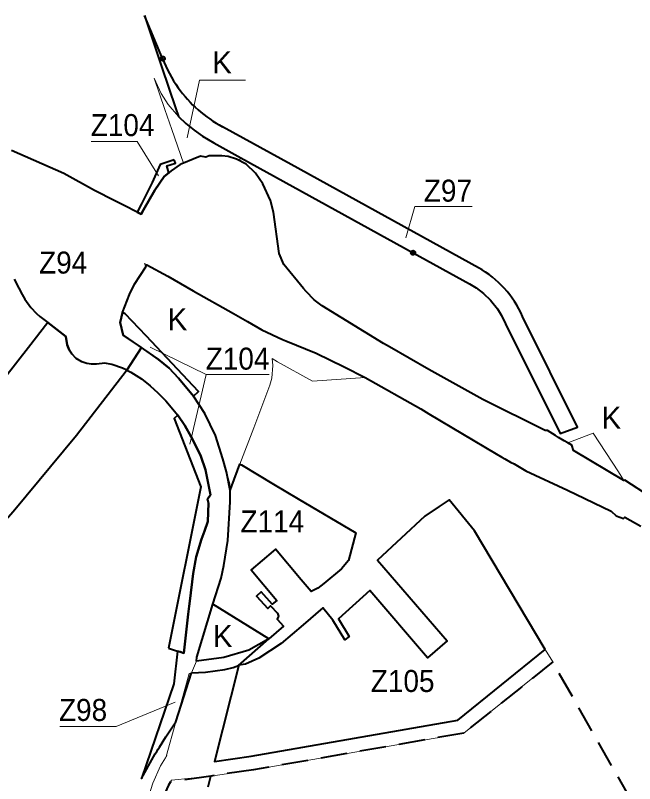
# Model space of a CAD drawing. Extents: x -650276 to -642489, y -1074311 to -1066658.
# Drawn here: x -646740 to -646064, y -1069193 to -1068354 of the extents above; entities that cross this region are included whole.
import ezdxf

# ---------------------------------------------------------------- set-up
doc = ezdxf.new("R2010")
doc.units = 0
doc.header["$LTSCALE"] = 9.6
doc.header["$PDMODE"] = 32
doc.header["$PDSIZE"] = 4.8
doc.linetypes.add('MEDIUM_DASHED', pattern=[4.5, 3, -1.5])
for name, color, linetype, lineweight in [('44', 7, 'Continuous', 40), ('45', 7, 'Continuous', 40), ('46', 7, 'Continuous', 13), ('47', 7, 'Continuous', 13), ('48', 7, 'Continuous', 13), ('61', 7, 'MEDIUM_DASHED', 40)]:
    doc.layers.add(name, color=color, linetype=linetype, lineweight=lineweight)

msp = doc.modelspace()

# ---------------------------------------------------------------- linework, layer by layer
at = {"layer": '44'}
msp.add_line((-646578.881, -1068401.54), (-646598.635, -1068354.436), dxfattribs=at)
for points in [[(-646598.635, -1068354.436), (-646579.62, -1068411.29), (-646564.78, -1068455.41), (-646561.544, -1068464.842)], [(-646561.544, -1068464.842), (-646553.677, -1068472.283), (-646544.525, -1068479.79), (-646535.245, -1068486.342), (-646523.105, -1068493.54), (-646493.511, -1068509.855), (-646305.678, -1068613.404)], [(-646234.342, -1068629.893), (-646234.342, -1068629.892), (-646438.626, -1068517.274), (-646513.45, -1068476.025), (-646513.567, -1068475.963)], [(-646545.57, -1068511.42), (-646556.22, -1068515.84), (-646559.72, -1068517.29), (-646569.61, -1068524.1), (-646572.02, -1068526.07), (-646577.07, -1068530.2), (-646587.28, -1068545.28), (-646599.75, -1068566.49), (-646602.21, -1068571.5), (-646606.59, -1068569.33), (-646620.94, -1068561.96), (-646625.86, -1068559.47), (-646631.18, -1068556.77), (-646653.21, -1068545.58), (-646686.84, -1068526.89), (-646686.84, -1068526.89), (-646743.69, -1068501.76)], [(-646337.93, -1068712.4), (-646404.83, -1068671.52), (-646413.45, -1068664.71), (-646422.32, -1068655.58), (-646425.11, -1068652.37), (-646446.54, -1068626.14), (-646451.82, -1068614.31), (-646458.03, -1068569.26), (-646461.14, -1068556.34), (-646469.51, -1068538.15), (-646477.41, -1068526.45), (-646487.92, -1068516.87), (-646498.48, -1068511.26), (-646507.4, -1068508.45), (-646514.39, -1068507.56), (-646528.18, -1068507.58), (-646531.9, -1068509.25), (-646537.71, -1068508.16), (-646545.57, -1068511.42)], [(-646305.678, -1068613.404), (-646243.997, -1068647.407), (-646236.707, -1068651.891), (-646228.691, -1068658.051), (-646221.348, -1068665.144), (-646213.659, -1068674.696), (-646209.179, -1068681.795), (-646204.654, -1068690.937), (-646145.083, -1068810.83), (-646126.317, -1068803.654), (-646186.371, -1068682.825)], [(-646602.095, -1068716.98), (-646622.01, -1068703.3), (-646625.35, -1068689.7), (-646622.68, -1068678.75), (-646615.19, -1068659.11), (-646609.7, -1068647.84), (-646597.4, -1068628.74), (-646596.28, -1068626.52), (-646596.28, -1068626.52), (-646573.14, -1068638.98), (-646545.73, -1068654.81), (-646545.73, -1068654.81), (-646501.64, -1068679.81), (-646486.23, -1068688.54), (-646470.65, -1068697.38), (-646448.02, -1068707.99), (-646444.51, -1068709.64), (-646411.3, -1068723.11), (-646380.94, -1068737.81), (-646357.87, -1068749.64), (-646297.08, -1068783.8), (-646288.37, -1068789.04), (-646251.73, -1068811.04), (-646214.92, -1068832.85), (-646208.7, -1068836.39), (-646205.48, -1068838.23), (-646199.24, -1068841.79), (-646195.52, -1068843.92), (-646182.57, -1068851.3), (-646137.23, -1068872.6), (-646089.63, -1068895.5), (-646084.1, -1068900.51), (-646076.09, -1068903.48), (-646074.51, -1068901.9), (-646057.13, -1068911.62)], [(-646740.91, -1068642.34), (-646735.62, -1068652.21), (-646732.25, -1068659.06), (-646729.34, -1068663.94), (-646722.6, -1068673.11), (-646716.39, -1068679.8), (-646716.39, -1068679.8), (-646712.93, -1068683), (-646704.316, -1068689.698), (-646684.7, -1068704.95), (-646682.98, -1068714.07), (-646680.88, -1068719.28), (-646678.08, -1068723.7)], [(-646704.316, -1068689.698), (-646725.374, -1068716.786), (-646751.116, -1068749.975), (-646817.718, -1068830.545), (-646855.506, -1068872.883), (-646894.206, -1068911.595), (-646934.465, -1068940.759)], [(-646617.991, -1068741.504), (-646622.62, -1068739.32), (-646634.37, -1068735.27), (-646642.04, -1068733.74), (-646651.21, -1068734.99), (-646656.47, -1068735.13), (-646661.5, -1068734.35), (-646667.17, -1068732.38), (-646673.16, -1068728.69), (-646678.08, -1068723.7), (-646680.88, -1068719.28), (-646682.98, -1068714.07), (-646684.7, -1068704.95), (-646704.316, -1068689.698)], [(-646046.48, -1068879.92), (-646074.78, -1068861.51), (-646075.56, -1068861.95), (-646130.68, -1068829.21), (-646132.62, -1068823.54), (-646136.99, -1068820.88), (-646140.73, -1068818.61), (-646146.85, -1068814.88), (-646150.26, -1068812.81), (-646159.1, -1068807.43), (-646161.45, -1068807.54), (-646229.44, -1068773.53), (-646288.59, -1068740.88), (-646331.26, -1068716.25), (-646337.93, -1068712.4)], [(-646618.655, -1068742.359), (-646617.991, -1068741.504), (-646617.991, -1068741.503), (-646602.095, -1068716.98)], [(-646539.08, -1068779.481), (-646545.32, -1068769.89), (-646561.5, -1068750.22), (-646571.91, -1068739.54), (-646583.49, -1068729.76), (-646602.095, -1068716.98), (-646617.991, -1068741.503)], [(-647065.688, -1069087.73), (-646978.92, -1069073.93), (-646929.186, -1069052.925), (-646880.163, -1069024.903), (-646829.104, -1068987.917), (-646782.784, -1068941.581), (-646741.85, -1068895.719), (-646673.05, -1068812.491), (-646618.655, -1068742.359), (-646617.991, -1068741.504)], [(-646617.991, -1068741.503), (-646613.44, -1068743.65), (-646601.86, -1068751.01), (-646592.53, -1068758.66), (-646583.98, -1068766.42), (-646575.28, -1068775.04), (-646562.49, -1068790.69), (-646554.8, -1068801.98)], [(-646509.323, -1068852.529), (-646513.27, -1068838.37), (-646521.18, -1068812.95), (-646532.92, -1068788.95), (-646539.08, -1068779.481)], [(-646554.8, -1068801.98), (-646547.68, -1068814.22), (-646547.433, -1068814.73)], [(-646547.433, -1068814.73), (-646537.35, -1068835.56), (-646532.16, -1068850.47), (-646526.64, -1068877.47), (-646530.06, -1068882.16)], [(-646524, -1068997), (-646514.91, -1068968.48), (-646514.91, -1068968.48), (-646512.07, -1068954.68), (-646507.91, -1068927.47), (-646505.12, -1068885.31), (-646505.17, -1068872.78), (-646509.323, -1068852.529)], [(-646530.06, -1068882.16), (-646528.92, -1068886.55), (-646529.44, -1068906.81), (-646533.28, -1068917.17)], [(-646533.28, -1068917.17), (-646536.54, -1068925.95), (-646542.16, -1068945.12), (-646545.42, -1068963.3), (-646549.17, -1068993.71), (-646549.81, -1068998.88), (-646550.89, -1069007.7), (-646555.84, -1069050.22), (-646559.8, -1069048.98), (-646562.61, -1069048.08)], [(-646462.98, -1069034.61), (-646485, -1069047), (-646512, -1069055), (-646542, -1069059), (-646541.71, -1069054.76), (-646524, -1068997)], [(-646547.412, -1069071.71), (-646532, -1069071), (-646511, -1069068), (-646502, -1069066), (-646496.317, -1069063.61), (-646462.98, -1069034.61)], [(-646562.61, -1069048.08), (-646566.82, -1069083.62), (-646601.82, -1069187.25), (-646586.97, -1069160.06), (-646585.42, -1069157.56), (-646583.89, -1069155.1), (-646582.46, -1069152.81), (-646582.46, -1069152.81), (-646575.4, -1069141.46), (-646564.54, -1069125.08), (-646547.412, -1069071.71)]]:
    msp.add_lwpolyline(points, dxfattribs=at)
at = {"layer": '44', "lineweight": 13}
for points in [[(-646241.379, -1068562.947), (-646303.746, -1068562.947), (-646313.477, -1068597.03)], [(-646241.379, -1068562.947), (-646303.746, -1068562.947), (-646313.477, -1068597.03)], [(-646691.216, -1069130.395), (-646629.734, -1069130.395), (-646565.156, -1069103.837)], [(-646691.216, -1069130.395), (-646629.734, -1069130.395), (-646565.156, -1069103.837)]]:
    msp.add_lwpolyline(points, dxfattribs=at)
at = {"layer": '44'}
for centre, radius, start, end in [((-646447.332, -1068351.964), 140.58, 200.6496, 215.36619), ((-646447.332, -1068351.964), 140.58, 215.36631, 241.891), ((-646287.447, -1068726.224), 110, 23.23727, 61.13296)]:
    msp.add_arc(centre, radius, start, end, dxfattribs=at)
for p in [(-646578.881, -1068401.54), (-646305.678, -1068613.404)]:
    msp.add_point(p, dxfattribs=at)
at = {"layer": '45'}
msp.add_line((-646583.49, -1068729.76), (-646571.91, -1068739.54), dxfattribs=at)
msp.add_line((-646583.49, -1068729.76), (-646571.91, -1068739.54), dxfattribs=at)
for points in [[(-646566.33, -1068512.04), (-646581.64, -1068517.24), (-646590.31, -1068536.69), (-646602.01, -1068560.15), (-646606.59, -1068569.33)], [(-646566.33, -1068512.04), (-646581.64, -1068517.24), (-646590.31, -1068536.69), (-646602.01, -1068560.15), (-646606.59, -1068569.33)], [(-646587.28, -1068545.28), (-646577.07, -1068530.2), (-646572.02, -1068526.07), (-646574.48, -1068518.75), (-646565.04, -1068515.86), (-646566.33, -1068512.04)], [(-646587.28, -1068545.28), (-646577.07, -1068530.2), (-646572.02, -1068526.07), (-646574.48, -1068518.75), (-646565.04, -1068515.86), (-646566.33, -1068512.04)], [(-646599.75, -1068566.49), (-646587.28, -1068545.28), (-646587.28, -1068545.28)], [(-646599.75, -1068566.49), (-646587.28, -1068545.28), (-646587.28, -1068545.28)], [(-646606.59, -1068569.33), (-646602.21, -1068571.5), (-646599.75, -1068566.49)], [(-646606.59, -1068569.33), (-646602.21, -1068571.5), (-646599.75, -1068566.49)], [(-646571.91, -1068739.54), (-646561.5, -1068750.22), (-646545.32, -1068769.89), (-646539.78, -1068764.65), (-646596.93, -1068704.15), (-646619.74, -1068680.15), (-646622.68, -1068678.75), (-646625.35, -1068689.7)], [(-646571.91, -1068739.54), (-646561.5, -1068750.22), (-646545.32, -1068769.89), (-646539.78, -1068764.65), (-646596.93, -1068704.15), (-646619.74, -1068680.15), (-646622.68, -1068678.75), (-646625.35, -1068689.7)], [(-646625.35, -1068689.7), (-646622.01, -1068703.3), (-646583.49, -1068729.76)], [(-646625.35, -1068689.7), (-646622.01, -1068703.3), (-646583.49, -1068729.76)], [(-646562.49, -1068790.69), (-646566.34, -1068794.32), (-646537.3, -1068868.95), (-646572.42, -1069044.94)], [(-646562.49, -1068790.69), (-646566.34, -1068794.32), (-646537.3, -1068868.95), (-646572.42, -1069044.94)], [(-646526.64, -1068877.47), (-646532.16, -1068850.47), (-646537.35, -1068835.56), (-646547.68, -1068814.22), (-646554.8, -1068801.98), (-646562.49, -1068790.69)], [(-646526.64, -1068877.47), (-646532.16, -1068850.47), (-646537.35, -1068835.56), (-646547.68, -1068814.22), (-646554.8, -1068801.98), (-646562.49, -1068790.69)], [(-646529.44, -1068906.81), (-646528.92, -1068886.55), (-646530.06, -1068882.16), (-646526.64, -1068877.47)], [(-646529.44, -1068906.81), (-646528.92, -1068886.55), (-646530.06, -1068882.16), (-646526.64, -1068877.47)], [(-646555.84, -1069050.22), (-646550.89, -1069007.7), (-646549.81, -1068998.88), (-646549.17, -1068993.71), (-646545.42, -1068963.3), (-646542.16, -1068945.12), (-646536.54, -1068925.95), (-646533.28, -1068917.17), (-646529.44, -1068906.81)], [(-646555.84, -1069050.22), (-646550.89, -1069007.7), (-646549.81, -1068998.88), (-646549.17, -1068993.71), (-646545.42, -1068963.3), (-646542.16, -1068945.12), (-646536.54, -1068925.95), (-646533.28, -1068917.17), (-646529.44, -1068906.81)], [(-646572.42, -1069044.94), (-646562.61, -1069048.08), (-646559.8, -1069048.98), (-646555.84, -1069050.22)], [(-646572.42, -1069044.94), (-646562.61, -1069048.08), (-646559.8, -1069048.98), (-646555.84, -1069050.22)]]:
    msp.add_lwpolyline(points, dxfattribs=at)
for points in [[(-646512.07, -1068954.68), (-646507.91, -1068927.47), (-646505.12, -1068885.31), (-646505.17, -1068872.78), (-646503.24, -1068867.61), (-646494.52, -1068844.29), (-646492.73, -1068845.01), (-646457.86, -1068865.8), (-646430.86, -1068881.89), (-646368.3, -1068919.19), (-646376.02, -1068949.34), (-646383.86, -1068958.24), (-646403.13, -1068974.41), (-646409.67, -1068979.3), (-646416.71, -1068983.21), (-646427.77, -1068970.39), (-646455.78, -1068936.87), (-646458.21, -1068938.99), (-646482.2, -1068959.52), (-646454.21, -1068992.73), (-646459.25, -1068996.98), (-646471.24, -1068983.41), (-646476.35, -1068987.98), (-646464.24, -1069001.49), (-646461.29, -1068998.81), (-646453.48, -1069006.75), (-646452.37, -1069010.01), (-646453.88, -1069013.1), (-646447.2, -1069020.9), (-646462.98, -1069034.61), (-646524, -1068997), (-646514.91, -1068968.48), (-646514.91, -1068968.48)], [(-646512.07, -1068954.68), (-646507.91, -1068927.47), (-646505.12, -1068885.31), (-646505.17, -1068872.78), (-646503.24, -1068867.61), (-646494.52, -1068844.29), (-646492.73, -1068845.01), (-646457.86, -1068865.8), (-646430.86, -1068881.89), (-646368.3, -1068919.19), (-646376.02, -1068949.34), (-646383.86, -1068958.24), (-646403.13, -1068974.41), (-646409.67, -1068979.3), (-646416.71, -1068983.21), (-646427.77, -1068970.39), (-646455.78, -1068936.87), (-646458.21, -1068938.99), (-646482.2, -1068959.52), (-646454.21, -1068992.73), (-646459.25, -1068996.98), (-646471.24, -1068983.41), (-646476.35, -1068987.98), (-646464.24, -1069001.49), (-646461.29, -1068998.81), (-646453.48, -1069006.75), (-646452.37, -1069010.01), (-646453.88, -1069013.1), (-646447.2, -1069020.9), (-646462.98, -1069034.61), (-646524, -1068997), (-646514.91, -1068968.48), (-646514.91, -1068968.48)], [(-646161.484, -1069046.228), (-646238.632, -1068916.799), (-646266.118, -1068883.048), (-646277.268, -1068890.446), (-646292.75, -1068900.72), (-646344.49, -1068948.736), (-646268.528, -1069036.82), (-646290.099, -1069055.423), (-646352.71, -1068981.82), (-646386.936, -1069012.936), (-646375.346, -1069032.07), (-646379.973, -1069035.889), (-646393.09, -1069014.234), (-646404.269, -1069001.033), (-646425.52, -1069019.41), (-646449.418, -1069039.804), (-646474.13, -1069055.83), (-646488.537, -1069062.169), (-646495.89, -1069063.531), (-646522.35, -1069168.648), (-646482.211, -1069162.813), (-646256.824, -1069123.414)], [(-646161.484, -1069046.228), (-646238.632, -1068916.799), (-646266.118, -1068883.048), (-646277.268, -1068890.446), (-646292.75, -1068900.72), (-646344.49, -1068948.736), (-646268.528, -1069036.82), (-646290.099, -1069055.423), (-646352.71, -1068981.82), (-646386.936, -1069012.936), (-646375.346, -1069032.07), (-646379.973, -1069035.889), (-646393.09, -1069014.234), (-646404.269, -1069001.033), (-646425.52, -1069019.41), (-646449.418, -1069039.804), (-646474.13, -1069055.83), (-646488.537, -1069062.169), (-646495.89, -1069063.531), (-646522.35, -1069168.648), (-646482.211, -1069162.813), (-646256.824, -1069123.414)]]:
    msp.add_lwpolyline(points, close=True, dxfattribs=at)
at = {"layer": '46'}
for points in [[(-646656.853, -1068492.089), (-646606.877, -1068492.089), (-646583.419, -1068529.344)], [(-646656.853, -1068492.089), (-646606.877, -1068492.089), (-646583.419, -1068529.344)], [(-646462.83, -1068746.366), (-646531.233, -1068746.366), (-646549.233, -1068822.328), (-646531.233, -1068746.366), (-646592.58, -1068716.54)], [(-646462.83, -1068746.366), (-646531.233, -1068746.366), (-646549.233, -1068822.328), (-646531.233, -1068746.366), (-646592.58, -1068716.54)]]:
    msp.add_lwpolyline(points, dxfattribs=at)
at = {"layer": '47'}
msp.add_line((-646462.98, -1069034.61), (-646524, -1068997), dxfattribs=at)
for points in [[(-646561.544, -1068464.842), (-646572.984, -1068451.81), (-646580.625, -1068439.803), (-646588.07, -1068422.96), (-646576.4, -1068457.27), (-646568.87, -1068479.14), (-646556.22, -1068515.84), (-646545.57, -1068511.42), (-646537.71, -1068508.16)], [(-646523.105, -1068493.54), (-646535.245, -1068486.342), (-646544.525, -1068479.79), (-646553.677, -1068472.283), (-646561.544, -1068464.842)], [(-646537.71, -1068508.16), (-646531.9, -1068509.25), (-646528.18, -1068507.58), (-646514.39, -1068507.56), (-646507.4, -1068508.45), (-646498.48, -1068511.26), (-646495.416, -1068512.888), (-646493.511, -1068509.855), (-646523.105, -1068493.54)], [(-646075.56, -1068861.95), (-646130.68, -1068829.21), (-646132.62, -1068823.54), (-646136.99, -1068820.88), (-646109.35, -1068810.23)], [(-646109.35, -1068810.23), (-646081.72, -1068852.51), (-646075.56, -1068861.95)], [(-646524, -1068997), (-646541.71, -1069054.76), (-646542, -1069059), (-646547.412, -1069071.71)], [(-646495.89, -1069063.531), (-646496.317, -1069063.61), (-646496.317, -1069063.61), (-646462.98, -1069034.61)], [(-646593.793, -1069255.911), (-646577.878, -1069206.485), (-646572.586, -1069194.485), (-646569.114, -1069188.86), (-646526.31, -1069184.381), (-646479.84, -1069177.626), (-646250.409, -1069137.52), (-646153.307, -1069059.947), (-646161.484, -1069046.228), (-646256.824, -1069123.414)], [(-646256.824, -1069123.414), (-646482.211, -1069162.813), (-646522.35, -1069168.648), (-646495.89, -1069063.531)], [(-646547.412, -1069071.71), (-646549.91, -1069072.542), (-646564.54, -1069125.08), (-646564.605, -1069125.271), (-646574.978, -1069163.017), (-646574.978, -1069163.017), (-646574.33, -1069162.04), (-646575.87, -1069164.54), (-646581.29, -1069173.32), (-646589.56, -1069192.07), (-646601.41, -1069229.34)]]:
    msp.add_lwpolyline(points, dxfattribs=at)
msp.add_lwpolyline([(-646513.27, -1068838.37), (-646505.69, -1068865.56), (-646505.17, -1068872.78), (-646503.24, -1068867.61), (-646494.52, -1068844.29), (-646479.45, -1068804.37), (-646461.92, -1068757.93), (-646459.59, -1068750.19), (-646458.57, -1068736.31), (-646459.54, -1068728.94), (-646453.51, -1068732.3), (-646415.3, -1068753.62), (-646357.87, -1068749.64), (-646411.3, -1068723.11), (-646448.02, -1068707.99), (-646470.65, -1068697.38), (-646486.23, -1068688.54), (-646501.64, -1068679.81), (-646545.73, -1068654.81), (-646573.14, -1068638.98), (-646598.59, -1068625.34), (-646597.4, -1068628.74), (-646609.7, -1068647.84), (-646615.19, -1068659.11), (-646622.68, -1068678.75), (-646619.74, -1068680.15), (-646596.93, -1068704.15), (-646539.78, -1068764.65), (-646545.32, -1068769.89), (-646532.92, -1068788.95), (-646521.18, -1068812.95)], close=True, dxfattribs=at)
at = {"layer": '48'}
msp.add_lwpolyline([(-646488.64, -1068425), (-646538.869, -1068425), (-646552.014, -1068487.951)], dxfattribs=at)
msp.add_lwpolyline([(-646488.64, -1068425), (-646538.869, -1068425), (-646552.014, -1068487.951)], dxfattribs=at)
at = {"layer": '61'}
for points in [[(-646583.457, -1069759.191), (-646554.262, -1069762.602), (-646321.973, -1069686.855), (-646209.9, -1069538.5), (-646146.8, -1069506.6), (-646148.5, -1069503), (-646028.16, -1069441.58), (-646023.96, -1069440.34), (-646075.49, -1069318.19), (-646025.14, -1069285.394), (-646153.307, -1069059.947)], [(-646153.307, -1069059.947), (-646250.409, -1069137.52), (-646479.84, -1069177.626), (-646526.31, -1069184.381)]]:
    msp.add_lwpolyline(points, dxfattribs=at)
msp.add_lwpolyline([(-646572.586, -1069194.485), (-646577.878, -1069206.485), (-646611.107, -1069309.68), (-646626.774, -1069359.349), (-646580.797, -1069364.111), (-646571.479, -1069363.822), (-646526.31, -1069184.381), (-646570.296, -1069190.776)], close=True, dxfattribs=at)

# ---------------------------------------------------------------- texts
at = {"layer": '44', "width": 0.95}
for s, p in [('Z97', (-646293.907, -1068557.715)), ('Z97', (-646293.907, -1068557.715)), ('Z94', (-646713.687, -1068636.144)), ('Z94', (-646713.687, -1068636.144)), ('Z98', (-646691.993, -1069124.279)), ('Z98', (-646691.993, -1069124.279))]:
    msp.add_text(s, height=24, dxfattribs=at).set_placement(p)
at = {"layer": '46', "width": 0.95}
for s, p in [('Z104', (-646657.338, -1068486.184)), ('Z104', (-646657.338, -1068486.184)), ('Z104', (-646531.893, -1068740.983)), ('Z104', (-646531.893, -1068740.983)), ('Z114', (-646493.997, -1068918.587)), ('Z114', (-646493.997, -1068918.587)), ('Z105', (-646351.762, -1069092.692)), ('Z105', (-646351.762, -1069092.692))]:
    msp.add_text(s, height=24, dxfattribs=at).set_placement(p)
at = {"layer": '48'}
for p in [(-646524.8, -1068417.662), (-646524.8, -1068417.662), (-646573.463, -1068697.908), (-646573.463, -1068697.908), (-646099.972, -1068805.526), (-646524.065, -1069043.743), (-646524.065, -1069043.743)]:
    msp.add_text('K', height=24, dxfattribs=at).set_placement(p)

doc.saveas('drawing.dxf')
